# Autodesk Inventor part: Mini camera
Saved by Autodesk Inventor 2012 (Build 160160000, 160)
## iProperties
Created: 2013-08
Part Number: Mini camera
Material: Default
Document SubType Name: Modeling
Designer: hilarion
Density: 1 g/cm^3
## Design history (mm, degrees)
node "Mini camera1"
node "Mini camera"
node "Base1"
